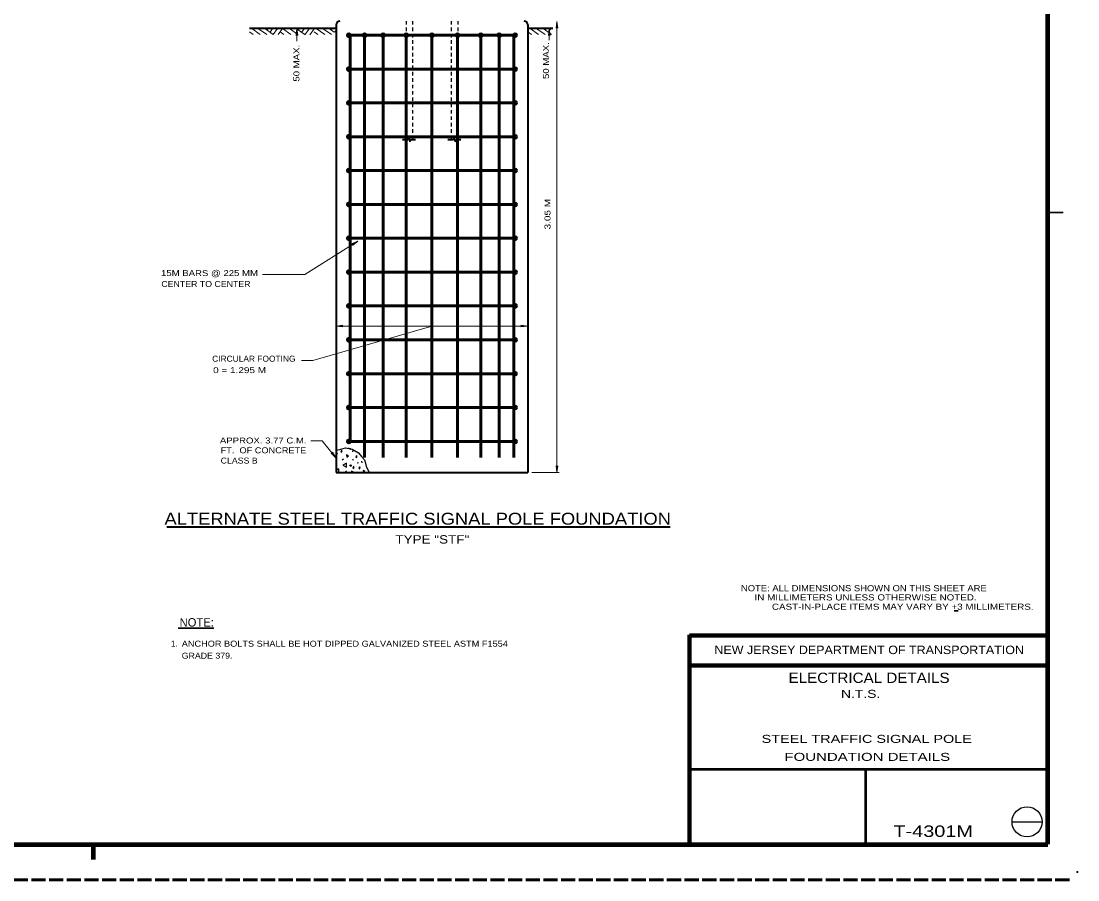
# Model space of a CAD drawing. Extents: x 312583 to 312853, y 144419 to 144586.
# Drawn here: x 312718.1 to 312852.8, y 144418.6 to 144528 of the extents above; entities that cross this region are included whole.
import ezdxf
from ezdxf.enums import TextEntityAlignment as Align

# ---------------------------------------------------------------- set-up
doc = ezdxf.new("R2010")
doc.units = 0
doc.header["$LTSCALE"] = 0.3
doc.header["$PDMODE"] = 32
doc.header["$PDSIZE"] = 0.15
doc.linetypes.add('LONG_DASHED', pattern=[7.5, 6, -1.5])
doc.linetypes.add('SHORT_DASHED', pattern=[2.7, 1.5, -1.2])
for name, color, linetype, lineweight in [('1', 7, 'Continuous', 13), ('10', 7, 'Continuous', 25), ('6', 7, 'Continuous', 35), ('61', 7, 'LONG_DASHED', 60)]:
    doc.layers.add(name, color=color, linetype=linetype, lineweight=lineweight)
doc.layers.add('2', color=7, linetype='Continuous')
doc.layers.add('5', color=7, linetype='Continuous')

msp = doc.modelspace()

# ---------------------------------------------------------------- linework, layer by layer
at = {"layer": '1', "lineweight": 158}
for p, q in [((312849, 144423.1446), (312849, 144585.0846)), ((312616.5, 144423.0846), (312849, 144423.0846)), ((312727.35, 144421.1646), (312727.35, 144423.0846))]:
    msp.add_line(p, q, dxfattribs=at)
at = {"layer": '1', "lineweight": 40}
for p, q in [((312758.2768, 144527.5325), (312758.2768, 144470.4772)), ((312782.7105, 144527.5325), (312782.7105, 144470.4772)), ((312758.2768, 144527.0572), (312747.2445, 144527.0572)), ((312785.8998, 144527.0572), (312782.7105, 144527.0572)), ((312767.4692, 144512.8815), (312766.7408, 144512.8815)), ((312767.8142, 144512.9429), (312768.4198, 144512.9429)), ((312773.2345, 144512.8815), (312772.5062, 144512.8815)), ((312773.5718, 144512.9429), (312774.1775, 144512.9429)), ((312758.2768, 144470.4772), (312782.7105, 144470.4772)), ((312736.7031, 144463.555), (312800.8805, 144463.555))]:
    msp.add_line(p, q, dxfattribs=at)
at = {"layer": '1', "linetype": 'SHORT_DASHED', "lineweight": 25}
for p, q in [((312767.1932, 144528.0155), (312767.1932, 144512.8815)), ((312768.0365, 144528.0155), (312768.0365, 144512.9429)), ((312772.9585, 144528.0155), (312772.9585, 144512.8815)), ((312773.7942, 144528.0155), (312773.7942, 144512.9429))]:
    msp.add_line(p, q, dxfattribs=at)
at = {"layer": '1'}
for p, q in [((312786.4288, 144527.9772), (312786.3215, 144527.1109)), ((312786.3215, 144527.1109), (312786.4288, 144527.3869)), ((312786.4288, 144527.9772), (312786.4288, 144470.4772)), ((312786.4288, 144527.9772), (312786.5362, 144527.1109)), ((312786.5362, 144527.1109), (312786.4288, 144527.3869)), ((312747.7275, 144526.2905), (312747.2445, 144526.6355)), ((312748.6092, 144526.2905), (312747.5358, 144527.0572)), ((312749.4525, 144526.2905), (312748.4098, 144527.0342)), ((312750.2805, 144526.2905), (312749.1918, 144527.0649)), ((312749.5675, 144527.0572), (312749.4448, 144526.8809)), ((312750.1962, 144527.0572), (312749.8665, 144526.5895)), ((312750.8248, 144527.0572), (312750.2805, 144526.2905)), ((312751.4535, 144527.0572), (312750.9092, 144526.2905)), ((312751.6375, 144526.2905), (312751.1545, 144526.6355)), ((312752.5192, 144526.2905), (312751.4535, 144527.0572)), ((312753.4008, 144526.2905), (312752.3275, 144527.0572)), ((312753.2935, 144527.0572), (312753.1862, 144526.1909)), ((312753.1862, 144526.1909), (312753.2935, 144526.4669)), ((312754.2825, 144526.2905), (312753.2092, 144527.0572)), ((312753.2935, 144525.4472), (312753.2935, 144527.0572)), ((312753.2935, 144527.0572), (312753.4008, 144526.1909)), ((312753.4008, 144526.1909), (312753.2935, 144526.4669)), ((312753.5848, 144527.0419), (312753.4622, 144526.8732)), ((312754.2135, 144527.0419), (312753.8838, 144526.5742)), ((312754.8422, 144527.0419), (312754.2978, 144526.2829)), ((312755.4708, 144527.0419), (312754.9265, 144526.2829)), ((312755.9538, 144526.2905), (312755.4708, 144526.6355)), ((312756.8355, 144526.2905), (312755.7622, 144527.0572)), ((312757.6788, 144526.2905), (312756.6362, 144527.0342)), ((312758.0315, 144526.6279), (312757.4182, 144527.0649)), ((312757.7938, 144527.0572), (312757.6712, 144526.8809)), ((312758.2308, 144526.7812), (312758.0928, 144526.5895)), ((312782.7105, 144527.0572), (312785.8998, 144527.0572)), ((312783.2012, 144526.2905), (312782.7105, 144526.6355)), ((312784.0828, 144526.2905), (312783.0095, 144527.0572)), ((312784.9185, 144526.2905), (312783.8835, 144527.0342)), ((312785.7542, 144526.2905), (312784.6655, 144527.0649)), ((312785.0412, 144527.0572), (312784.9185, 144526.8809)), ((312785.6698, 144527.0572), (312785.3402, 144526.5895)), ((312785.4552, 144527.0572), (312785.3478, 144526.1909)), ((312785.3478, 144526.1909), (312785.4552, 144526.4669)), ((312785.4552, 144527.0572), (312785.4552, 144525.6082)), ((312785.4552, 144527.0572), (312785.5625, 144526.1909)), ((312785.5625, 144526.1909), (312785.4552, 144526.4669)), ((312761.0368, 144499.9939), (312760.2548, 144499.6259)), ((312760.2548, 144499.6259), (312760.5385, 144499.6795)), ((312761.0368, 144499.9939), (312760.3622, 144499.4419)), ((312760.3622, 144499.4419), (312760.5385, 144499.6795)), ((312770.4975, 144489.1532), (312755.3175, 144484.7832)), ((312758.2768, 144489.1532), (312759.1432, 144489.2605)), ((312782.7105, 144489.1532), (312758.2768, 144489.1532)), ((312758.2768, 144489.1532), (312759.1432, 144489.0459)), ((312759.1432, 144489.2605), (312758.8672, 144489.1532)), ((312759.1432, 144489.0459), (312758.8672, 144489.1532)), ((312781.8442, 144489.2605), (312782.1202, 144489.1532)), ((312782.7105, 144489.1532), (312781.8442, 144489.2605)), ((312781.8442, 144489.0459), (312782.1202, 144489.1532)), ((312782.7105, 144489.1532), (312781.8442, 144489.0459)), ((312755.3175, 144484.7832), (312753.8685, 144484.7832)), ((312756.5135, 144474.5175), (312755.0645, 144474.5175)), ((312756.5135, 144474.5175), (312758.2768, 144472.3325)), ((312757.6482, 144472.9459), (312757.9088, 144472.7925)), ((312758.2768, 144472.3325), (312757.6482, 144472.9459)), ((312757.8168, 144473.0762), (312757.9088, 144472.7925)), ((312758.2768, 144472.3325), (312757.8168, 144473.0762)), ((312786.3215, 144471.3435), (312786.4288, 144471.0675)), ((312786.4288, 144470.4772), (312786.3215, 144471.3435)), ((312786.5362, 144471.3435), (312786.4288, 144471.0675)), ((312786.4288, 144470.4772), (312786.5362, 144471.3435)), ((312783.2088, 144470.4772), (312786.7202, 144470.4772))]:
    msp.add_line(p, q, dxfattribs=at)
at = {"layer": '1', "lineweight": 60}
for p, q in [((312760.0708, 144526.2139), (312760.0708, 144474.4332)), ((312760.0708, 144526.2139), (312780.9165, 144526.2139)), ((312761.9185, 144526.2139), (312761.9185, 144472.4015)), ((312764.2645, 144526.2139), (312764.2645, 144472.4015)), ((312767.2162, 144526.2139), (312767.2162, 144472.4015)), ((312770.4975, 144526.2139), (312770.4975, 144472.4015)), ((312773.7712, 144526.2139), (312773.7712, 144472.4015)), ((312776.7228, 144526.2139), (312776.7228, 144472.4015)), ((312779.0688, 144526.2139), (312779.0688, 144472.4015)), ((312780.9165, 144526.2139), (312780.9165, 144472.4015)), ((312760.0708, 144521.9052), (312780.9165, 144521.9052)), ((312760.0708, 144517.5889), (312780.9165, 144517.5889)), ((312760.0708, 144513.2802), (312780.9165, 144513.2802)), ((312760.0708, 144508.9639), (312780.9165, 144508.9639)), ((312760.0708, 144504.6552), (312780.9165, 144504.6552)), ((312760.0708, 144500.3389), (312780.9165, 144500.3389)), ((312760.0708, 144496.0302), (312780.9165, 144496.0302)), ((312760.0708, 144491.7139), (312780.9165, 144491.7139)), ((312760.0708, 144487.4052), (312780.9165, 144487.4052)), ((312760.0708, 144483.0889), (312780.9165, 144483.0889)), ((312760.0708, 144478.7802), (312780.9165, 144478.7802)), ((312760.0708, 144474.4639), (312780.9165, 144474.4639))]:
    msp.add_line(p, q, dxfattribs=at)
at = {"layer": '1', "lineweight": 35}
for p, q in [((312767.5918, 144513.2112), (312767.4692, 144512.8815)), ((312767.5918, 144513.2112), (312767.6915, 144512.6209)), ((312767.8142, 144512.9429), (312767.6915, 144512.6209)), ((312773.3495, 144513.2112), (312773.2345, 144512.8815)), ((312773.3495, 144513.2112), (312773.4568, 144512.6209)), ((312773.5718, 144512.9429), (312773.4568, 144512.6209)), ((312849, 144503.6216), (312850.932, 144503.6216)), ((312837.0395, 144452.8853), (312837.5494, 144452.8853))]:
    msp.add_line(p, q, dxfattribs=at)
at = {"layer": '1', "lineweight": 25}
for p, q in [((312759.8178, 144473.6282), (312760.1092, 144473.4519)), ((312760.1092, 144473.4519), (312760.1092, 144473.5822)), ((312758.3305, 144472.9612), (312758.4532, 144472.9305)), ((312759.2122, 144472.1945), (312759.0358, 144472.0642)), ((312760.3238, 144473.2142), (312760.4772, 144473.2295)), ((312760.3698, 144472.2405), (312760.4542, 144472.0719)), ((312759.4882, 144470.6229), (312759.6108, 144470.6919)), ((312760.9755, 144471.7115), (312761.1212, 144471.7575)), ((312761.5352, 144471.9492), (312761.5582, 144471.7345)), ((312758.2768, 144470.6459), (312758.5528, 144470.4849)), ((312759.3885, 144470.5002), (312759.4652, 144470.5155))]:
    msp.add_line(p, q, dxfattribs=at)
at = {"layer": '1', "lineweight": 80}
for p, q in [((312803.31, 144423.1446), (312803.31, 144449.8146)), ((312803.31, 144449.7246), (312849, 144449.7246)), ((312803.31, 144445.9146), (312849, 144445.9146))]:
    msp.add_line(p, q, dxfattribs=at)
at = {"layer": '1', "lineweight": 53}
for p, q in [((312849, 144432.6666), (312803.1226, 144432.6666)), ((312825.7546, 144432.6666), (312825.7546, 144423.1446))]:
    msp.add_line(p, q, dxfattribs=at)
at = {"layer": '1'}
msp.add_lwpolyline([(312761.0368, 144499.9939), (312754.2902, 144495.7235), (312748.8852, 144495.7235)], dxfattribs=at)
at = {"layer": '1', "lineweight": 25}
for points in [[(312758.3382, 144473.3522), (312758.8902, 144473.4519), (312759.4882, 144473.6512), (312760.3392, 144473.4519), (312761.1365, 144473.0072), (312761.5352, 144472.5549), (312761.8878, 144472.1025), (312762.0335, 144471.7039), (312762.1332, 144471.2592), (312762.4858, 144470.5539)], [(312758.3075, 144472.0259), (312758.3535, 144472.0642), (312758.3075, 144472.0949)], [(312758.6448, 144470.4849), (312758.6448, 144470.9449), (312758.2845, 144470.7609)], [(312760.4618, 144470.5232), (312760.4925, 144470.5385), (312760.2548, 144470.6765), (312760.2778, 144470.5155)], [(312761.8802, 144470.5462), (312761.9645, 144470.6152), (312761.7345, 144470.7532), (312761.7652, 144470.5462)]]:
    msp.add_lwpolyline(points, dxfattribs=at)
for points in [[(312759.0282, 144473.1912), (312759.0742, 144473.2755), (312758.9592, 144473.3062), (312758.8978, 144473.1529), (312759.0282, 144473.0839)], [(312759.6645, 144472.4629), (312759.8562, 144472.6085), (312759.6262, 144472.7465)], [(312760.9372, 144472.5012), (312760.9832, 144472.5855), (312760.8605, 144472.6162), (312760.8068, 144472.4629), (312760.9372, 144472.3939)], [(312759.5878, 144471.1672), (312759.5878, 144471.6809), (312759.1202, 144471.4432)], [(312760.5538, 144471.1289), (312760.5998, 144471.2132), (312760.4848, 144471.2439), (312760.4235, 144471.0905), (312760.5538, 144471.0215)], [(312761.3205, 144471.0752), (312761.3665, 144471.1595), (312761.2515, 144471.1902), (312761.1902, 144471.0445), (312761.3205, 144470.9679)]]:
    msp.add_lwpolyline(points, close=True, dxfattribs=at)
at = {"layer": '1', "lineweight": 60}
for centre, radius in [((312759.8931, 144526.2148), 0.1797), ((312759.8931, 144526.2148), 0.0898), ((312761.9175, 144526.2148), 0.1797), ((312761.9175, 144526.2148), 0.0898), ((312764.2626, 144526.2148), 0.1797), ((312764.2626, 144526.2148), 0.0898), ((312767.2181, 144526.2148), 0.1797), ((312767.2181, 144526.2148), 0.0898), ((312770.4946, 144526.2148), 0.1797), ((312770.4946, 144526.2148), 0.0898), ((312773.7702, 144526.2148), 0.1797), ((312773.7702, 144526.2148), 0.0898), ((312776.7252, 144526.2148), 0.1797), ((312776.7252, 144526.2148), 0.0898), ((312779.0717, 144526.2148), 0.1797), ((312779.0717, 144526.2148), 0.0898), ((312781.0962, 144526.2148), 0.1797), ((312781.0962, 144526.2148), 0.0898), ((312759.8931, 144521.9023), 0.1797), ((312759.8931, 144521.9023), 0.0898), ((312781.0962, 144521.9023), 0.1797), ((312781.0962, 144521.9023), 0.0898), ((312759.8931, 144517.5898), 0.1797), ((312759.8931, 144517.5898), 0.0898), ((312781.0962, 144517.5898), 0.1797), ((312781.0962, 144517.5898), 0.0898), ((312759.8931, 144513.2773), 0.1797), ((312759.8931, 144513.2773), 0.0898), ((312781.0962, 144513.2773), 0.1797), ((312781.0962, 144513.2773), 0.0898), ((312759.8931, 144508.9648), 0.1797), ((312759.8931, 144508.9648), 0.0898), ((312781.0962, 144508.9648), 0.1797), ((312781.0962, 144508.9648), 0.0898), ((312759.8931, 144504.6523), 0.1797), ((312759.8931, 144504.6523), 0.0898), ((312781.0962, 144504.6523), 0.1797), ((312781.0962, 144504.6523), 0.0898), ((312759.8931, 144500.3398), 0.1797), ((312759.8931, 144500.3398), 0.0898), ((312781.0962, 144500.3398), 0.1797), ((312781.0962, 144500.3398), 0.0898), ((312759.8931, 144496.0273), 0.1797), ((312759.8931, 144496.0273), 0.0898), ((312781.0962, 144496.0273), 0.1797), ((312781.0962, 144496.0273), 0.0898), ((312759.8931, 144491.7148), 0.1797), ((312759.8931, 144491.7148), 0.0898), ((312781.0962, 144491.7148), 0.1797), ((312781.0962, 144491.7148), 0.0898), ((312759.8931, 144487.4023), 0.1797), ((312759.8931, 144487.4023), 0.0898), ((312781.0962, 144487.4023), 0.1797), ((312781.0962, 144487.4023), 0.0898), ((312759.8931, 144483.0898), 0.1797), ((312759.8931, 144483.0898), 0.0898), ((312781.0962, 144483.0898), 0.1797), ((312781.0962, 144483.0898), 0.0898), ((312759.8931, 144478.7773), 0.1797), ((312759.8931, 144478.7773), 0.0898), ((312781.0962, 144478.7773), 0.1797), ((312781.0962, 144478.7773), 0.0898), ((312759.8931, 144474.4648), 0.1797), ((312759.8931, 144474.4648), 0.0898), ((312781.0962, 144474.4648), 0.1797), ((312781.0962, 144474.4648), 0.0898)]:
    msp.add_circle(centre, radius, dxfattribs=at)
at = {"layer": '1', "lineweight": 25}
msp.add_circle((312760.1215, 144471.3734), 0.0865, dxfattribs=at)
at = {"layer": '1', "lineweight": 40}
for centre, start, end in [((312758.755, 144527.5325), 90, 180), ((312782.2342, 144527.5325), 0, 90)]:
    msp.add_arc(centre, 0.4792, start, end, dxfattribs=at)
at = {"layer": '1'}
msp.add_point((312852.75, 144419.5846), dxfattribs=at)
at = {"layer": '10'}
msp.add_line((312844.4383, 144425.9659), (312848.2793, 144425.9659), dxfattribs=at)
msp.add_circle((312846.3494, 144425.9805), 1.9159, dxfattribs=at)
at = {"layer": '6'}
msp.add_line((312738.1609, 144450.6386), (312742.715, 144450.6386), dxfattribs=at)
at = {"layer": '61'}
msp.add_line((312851.75, 144418.5846), (312583.526, 144418.5846), dxfattribs=at)

# ---------------------------------------------------------------- texts
at = {"layer": '1'}
for s, width, p in [('50 MAX.', 1.2, (312753.6097, 144520.3094)), ('50 MAX.', 1.2, (312785.4129, 144520.6423)), ('3.05 M', 1.25, (312785.6078, 144501.4682))]:
    msp.add_text(s, height=0.76, rotation=90, dxfattribs=dict(at, width=width)).set_placement(p)
for s, height, width, p in [('15M BARS @ 225 MM', 0.76, 1.2, (312735.9692, 144495.5248)), ('CENTER TO CENTER', 0.76, 1.1, (312736.0096, 144494.1372)), ('CIRCULAR FOOTING', 0.76, 1.05, (312742.492, 144484.6152)), ('0 = 1.295 M', 0.76, 1.25, (312742.61, 144483.1585)), ('APPROX. 3.77 C.M.', 0.76, 1.2, (312743.4738, 144474.1916)), ('FT.  OF CONCRETE', 0.76, 1.15, (312743.5686, 144472.9453)), ('CLASS B', 0.76, 1.1, (312743.5659, 144471.6343)), ('NOTE: ALL DIMENSIONS SHOWN ON THIS SHEET ARE', 0.78, 1.15, (312809.8816, 144455.3605)), ('     IN MILLIMETERS UNLESS OTHERWISE NOTED.', 0.78, 1.2, (312809.8815, 144454.1905)), ('CAST-IN-PLACE ITEMS MAY VARY BY +3 MILLIMETERS.', 0.78, 1.2, (312813.8324, 144452.9996))]:
    msp.add_text(s, height=height, dxfattribs=dict(at, width=width)).set_placement(p)
for s, height, width, p in [('ALTERNATE STEEL TRAFFIC SIGNAL POLE FOUNDATION', 1.52, 1.15, (312768.6846, 144463.8478)), ('TYPE "STF"', 1.07, 1.2, (312770.5491, 144461.435)), ('NEW JERSEY DEPARTMENT OF TRANSPORTATION', 1.08, 1.1, (312826.2285, 144447.3546)), ('ELECTRICAL DETAILS', 1.315, 1.1, (312826.2107, 144443.6759))]:
    msp.add_text(s, height=height, dxfattribs=dict(at, width=width)).set_placement(p, align=Align.CENTER)
at = {"layer": '2'}
for s, width, p in [('    N.T.S.  ', 1.3, (312824.6461, 144441.778)), ('    N.T.S.  ', 1.3, (312824.6461, 144441.778)), ('    N.T.S.  ', 1.3, (312824.6461, 144441.778)), ('    N.T.S.  ', 1.3, (312824.6461, 144441.778)), ('    N.T.S.  ', 1.3, (312824.6461, 144441.778)), ('    N.T.S.  ', 1.3, (312824.6461, 144441.778)), ('    N.T.S.  ', 1.3, (312824.6461, 144441.778)), ('    N.T.S.  ', 1.3, (312824.6461, 144441.778)), ('    N.T.S.  ', 1.3, (312824.6461, 144441.778)), ('    N.T.S.  ', 1.3, (312824.6461, 144441.778)), ('    N.T.S.  ', 1.3, (312824.6461, 144441.778)), ('    N.T.S.  ', 1.3, (312824.6461, 144441.778)), ('    N.T.S.  ', 1.3, (312824.6461, 144441.778)), ('    N.T.S.  ', 1.3, (312824.6461, 144441.778)), ('    N.T.S.  ', 1.3, (312824.6461, 144441.778)), ('       STEEL TRAFFIC SIGNAL POLE       ', 1.35, (312825.9194, 144436.0399)), ('           FOUNDATION DETAILS           ', 1.4, (312825.9846, 144433.7476))]:
    msp.add_text(s, height=1.02, dxfattribs=dict(at, width=width)).set_placement(p, align=Align.CENTER)
at = {"layer": '5', "width": 1.3}
msp.add_text('T-4301M  ', height=1.457, dxfattribs=at).set_placement((312835.0894, 144424.0569), align=Align.CENTER)
at = {"layer": '6'}
msp.add_text('NOTE:', height=1.07, dxfattribs=at).set_placement((312740.5209, 144450.8629), align=Align.CENTER)
msp.add_text('1. ', height=0.76, dxfattribs=at).set_placement((312737.2271, 144448.2992))
for s, width, p in [('ANCHOR BOLTS SHALL BE HOT DIPPED GALVANIZED STEEL ASTM F1554', 1.15, (312738.6105, 144448.2992)), ('GRADE 379.', 1.1, (312738.6105, 144446.7658))]:
    msp.add_text(s, height=0.76, dxfattribs=dict(at, width=width)).set_placement(p)

doc.saveas('drawing.dxf')
